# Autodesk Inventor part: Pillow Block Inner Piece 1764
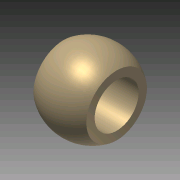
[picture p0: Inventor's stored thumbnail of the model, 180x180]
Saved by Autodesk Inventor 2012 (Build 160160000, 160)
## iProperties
Created: 2009-01
Part Number: Pillow Block Inner Piece 1764
Document SubType Name: Modeling
Designer: lwoods
Density: 1.4 g/cm^3
Material: PVC-Piping
Mass: 9.20302 g
Surface Area: 29.8864 cm^2
Volume: 6.57359 cm^3
Author: lwoods
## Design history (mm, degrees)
sketch "Sketch1"
  geometry: L1 (-16.593, 9.074)-(2.534, 9.074); L2 (-16.593, 9.074)-(-16.593, 12.071); L3 (2.534, 9.074)-(2.534, 12.071); L4 (-16.593, 12.071)-(2.534, 12.071); L5 (-7.029, 12.071)-(-7.029, 15.246); L6 (-28, 1.137)-(15.926, 1.137); A1 r 15.99 centre (-7.029, -0.743) between (2.534, 12.071) and (-16.593, 12.071)
  constraints: 12 end point, 3 point on circle, 2 perpendicular, 1 centre point, 1 horizontal, 1 midpoint, 1 parallel
  dimensions: "d0" = 0 vertical distance of L3.end L2.end; "d1" = 3.175 distance of L5.start L5.end; "d2" = 19.1262 distance of L1.start L1.end; "d3" = 2.9972 distance of L1.start L2.end; "d4" = 7.9375 distance from line of L6 L1.end
revolve "Revolution1" sketch "Sketch1" stored, may be unused: angle "d5" = 90 deg
body "Solid1"
